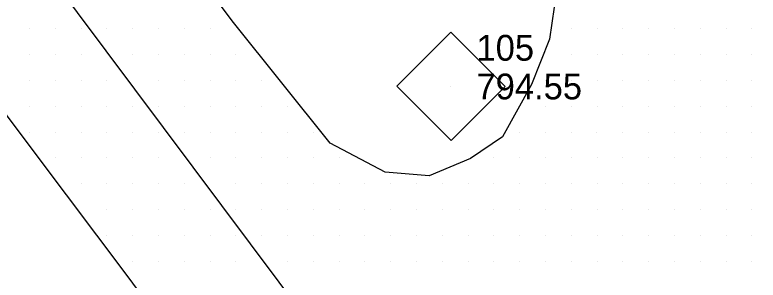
# Model space of a CAD drawing. Extents: x 1762120 to 1766775, y 709485 to 712965.
# Drawn here: x 1763947.3 to 1764019.4, y 711549.4 to 711575.1 of the extents above; entities that cross this region are included whole.
import ezdxf

# ---------------------------------------------------------------- set-up
doc = ezdxf.new("R2010")
doc.units = 0
for name, color, linetype in [('CTL Secondary Horizontal and Vertical CELL', 7, 'Continuous'), ('CTL Secondary Horizontal and Vertical Cogo Elevation', 7, 'Continuous'), ('CTL Secondary Horizontal and Vertical Cogo Number', 7, 'Continuous'), ('Exist DTM Scan Elevation Point', 7, 'Continuous'), ('Exist Roads EOP', 7, 'Continuous'), ('Exist Roads EOT', 7, 'Continuous')]:
    doc.layers.add(name, color=color, linetype=linetype)

msp = doc.modelspace()

# ---------------------------------------------------------------- linework, layer by layer
at = {"layer": 'CTL Secondary Horizontal and Vertical CELL'}
msp.add_line((1763989.569, 711568.173), (1763989.569, 711568.173), dxfattribs=at)
msp.add_lwpolyline([(1763984.354, 711568.191), (1763989.596, 711573.432), (1763994.846, 711568.182), (1763989.604, 711562.94)], close=True, dxfattribs=at)
at = {"layer": 'Exist DTM Scan Elevation Point'}
for p, q in [((1763948.75, 711573.75), (1763948.75, 711573.75)), ((1763951.25, 711573.75), (1763951.25, 711573.75)), ((1763953.75, 711573.75), (1763953.75, 711573.75)), ((1763956.25, 711573.75), (1763956.25, 711573.75)), ((1763958.75, 711573.75), (1763958.75, 711573.75)), ((1763961.25, 711573.75), (1763961.25, 711573.75)), ((1763963.75, 711573.75), (1763963.75, 711573.75)), ((1763966.25, 711573.75), (1763966.25, 711573.75)), ((1764001.25, 711573.75), (1764001.25, 711573.75)), ((1764003.75, 711573.75), (1764003.75, 711573.75)), ((1764006.25, 711573.75), (1764006.25, 711573.75)), ((1764008.75, 711573.75), (1764008.75, 711573.75)), ((1764011.25, 711573.75), (1764011.25, 711573.75)), ((1764013.75, 711573.75), (1764013.75, 711573.75)), ((1764016.25, 711573.75), (1764016.25, 711573.75)), ((1764018.75, 711573.75), (1764018.75, 711573.75)), ((1763948.75, 711571.25), (1763948.75, 711571.25)), ((1763951.25, 711571.25), (1763951.25, 711571.25)), ((1763953.75, 711571.25), (1763953.75, 711571.25)), ((1763958.75, 711571.25), (1763958.75, 711571.25)), ((1763961.25, 711571.25), (1763961.25, 711571.25)), ((1763963.75, 711571.25), (1763963.75, 711571.25)), ((1763966.25, 711571.25), (1763966.25, 711571.25)), ((1763968.75, 711571.25), (1763968.75, 711571.25)), ((1764001.25, 711571.25), (1764001.25, 711571.25)), ((1764003.75, 711571.25), (1764003.75, 711571.25)), ((1764006.25, 711571.25), (1764006.25, 711571.25)), ((1764008.75, 711571.25), (1764008.75, 711571.25)), ((1764011.25, 711571.25), (1764011.25, 711571.25)), ((1764013.75, 711571.25), (1764013.75, 711571.25)), ((1764016.25, 711571.25), (1764016.25, 711571.25)), ((1764018.75, 711571.25), (1764018.75, 711571.25)), ((1763948.75, 711568.75), (1763948.75, 711568.75)), ((1763951.25, 711568.75), (1763951.25, 711568.75)), ((1763953.75, 711568.75), (1763953.75, 711568.75)), ((1763956.25, 711568.75), (1763956.25, 711568.75)), ((1763961.25, 711568.75), (1763961.25, 711568.75)), ((1763963.75, 711568.75), (1763963.75, 711568.75)), ((1763966.25, 711568.75), (1763966.25, 711568.75)), ((1763968.75, 711568.75), (1763968.75, 711568.75)), ((1763971.25, 711568.75), (1763971.25, 711568.75)), ((1763998.75, 711568.75), (1763998.75, 711568.75)), ((1764001.25, 711568.75), (1764001.25, 711568.75)), ((1764003.75, 711568.75), (1764003.75, 711568.75)), ((1764006.25, 711568.75), (1764006.25, 711568.75)), ((1764008.75, 711568.75), (1764008.75, 711568.75)), ((1764011.25, 711568.75), (1764011.25, 711568.75)), ((1764013.75, 711568.75), (1764013.75, 711568.75)), ((1764016.25, 711568.75), (1764016.25, 711568.75)), ((1764018.75, 711568.75), (1764018.75, 711568.75)), ((1763948.75, 711566.25), (1763948.75, 711566.25)), ((1763951.25, 711566.25), (1763951.25, 711566.25)), ((1763953.75, 711566.25), (1763953.75, 711566.25)), ((1763956.25, 711566.25), (1763956.25, 711566.25)), ((1763958.75, 711566.25), (1763958.75, 711566.25)), ((1763961.25, 711566.25), (1763961.25, 711566.25)), ((1763963.75, 711566.25), (1763963.75, 711566.25)), ((1763966.25, 711566.25), (1763966.25, 711566.25)), ((1763968.75, 711566.25), (1763968.75, 711566.25)), ((1763971.25, 711566.25), (1763971.25, 711566.25)), ((1763973.75, 711566.25), (1763973.75, 711566.25)), ((1763998.75, 711566.25), (1763998.75, 711566.25)), ((1764001.25, 711566.25), (1764001.25, 711566.25)), ((1764003.75, 711566.25), (1764003.75, 711566.25)), ((1764006.25, 711566.25), (1764006.25, 711566.25)), ((1764008.75, 711566.25), (1764008.75, 711566.25)), ((1764011.25, 711566.25), (1764011.25, 711566.25)), ((1764013.75, 711566.25), (1764013.75, 711566.25)), ((1764016.25, 711566.25), (1764016.25, 711566.25)), ((1764018.75, 711566.25), (1764018.75, 711566.25)), ((1763948.75, 711563.75), (1763948.75, 711563.75)), ((1763951.25, 711563.75), (1763951.25, 711563.75)), ((1763953.75, 711563.75), (1763953.75, 711563.75)), ((1763956.25, 711563.75), (1763956.25, 711563.75)), ((1763958.75, 711563.75), (1763958.75, 711563.75)), ((1763961.25, 711563.75), (1763961.25, 711563.75)), ((1763963.75, 711563.75), (1763963.75, 711563.75)), ((1763966.25, 711563.75), (1763966.25, 711563.75)), ((1763968.75, 711563.75), (1763968.75, 711563.75)), ((1763971.25, 711563.75), (1763971.25, 711563.75)), ((1763973.75, 711563.75), (1763973.75, 711563.75)), ((1763976.25, 711563.75), (1763976.25, 711563.75)), ((1763996.25, 711563.75), (1763996.25, 711563.75)), ((1763998.75, 711563.75), (1763998.75, 711563.75)), ((1764001.25, 711563.75), (1764001.25, 711563.75)), ((1764003.743, 711563.748), (1764003.743, 711563.748)), ((1764006.25, 711563.75), (1764006.25, 711563.75)), ((1764008.75, 711563.75), (1764008.75, 711563.75)), ((1764011.25, 711563.75), (1764011.25, 711563.75)), ((1764013.75, 711563.75), (1764013.75, 711563.75)), ((1764016.25, 711563.75), (1764016.25, 711563.75)), ((1764018.75, 711563.75), (1764018.75, 711563.75)), ((1763951.25, 711561.25), (1763951.25, 711561.25)), ((1763953.75, 711561.25), (1763953.75, 711561.25)), ((1763956.25, 711561.25), (1763956.25, 711561.25)), ((1763958.75, 711561.25), (1763958.75, 711561.25)), ((1763961.25, 711561.25), (1763961.25, 711561.25)), ((1763966.25, 711561.25), (1763966.25, 711561.25)), ((1763968.75, 711561.25), (1763968.75, 711561.25)), ((1763971.25, 711561.25), (1763971.25, 711561.25)), ((1763973.75, 711561.25), (1763973.75, 711561.25)), ((1763976.25, 711561.25), (1763976.25, 711561.25)), ((1763978.75, 711561.25), (1763978.75, 711561.25)), ((1763993.75, 711561.25), (1763993.75, 711561.25)), ((1763996.25, 711561.25), (1763996.25, 711561.25)), ((1763998.75, 711561.25), (1763998.75, 711561.25)), ((1764001.25, 711561.25), (1764001.25, 711561.25)), ((1764003.75, 711561.25), (1764003.75, 711561.25)), ((1764006.25, 711561.25), (1764006.25, 711561.25)), ((1764008.75, 711561.25), (1764008.75, 711561.25)), ((1764011.25, 711561.25), (1764011.25, 711561.25)), ((1764013.75, 711561.25), (1764013.75, 711561.25)), ((1764016.25, 711561.25), (1764016.25, 711561.25)), ((1764018.75, 711561.25), (1764018.75, 711561.25)), ((1763953.75, 711558.75), (1763953.75, 711558.75)), ((1763956.25, 711558.75), (1763956.25, 711558.75)), ((1763958.75, 711558.75), (1763958.75, 711558.75)), ((1763961.25, 711558.75), (1763961.25, 711558.75)), ((1763963.75, 711558.75), (1763963.75, 711558.75)), ((1763968.75, 711558.75), (1763968.75, 711558.75)), ((1763971.25, 711558.75), (1763971.25, 711558.75)), ((1763973.75, 711558.75), (1763973.75, 711558.75)), ((1763976.25, 711558.75), (1763976.25, 711558.75)), ((1763978.75, 711558.75), (1763978.75, 711558.75)), ((1763981.25, 711558.75), (1763981.25, 711558.75)), ((1763983.75, 711558.75), (1763983.75, 711558.75)), ((1763986.25, 711558.75), (1763986.25, 711558.75)), ((1763988.75, 711558.75), (1763988.75, 711558.75)), ((1763991.25, 711558.75), (1763991.25, 711558.75)), ((1763993.75, 711558.75), (1763993.75, 711558.75)), ((1763996.25, 711558.75), (1763996.25, 711558.75)), ((1763998.75, 711558.75), (1763998.75, 711558.75)), ((1764001.25, 711558.75), (1764001.25, 711558.75)), ((1764003.75, 711558.75), (1764003.75, 711558.75)), ((1764006.25, 711558.75), (1764006.25, 711558.75)), ((1764008.75, 711558.75), (1764008.75, 711558.75)), ((1764011.25, 711558.75), (1764011.25, 711558.75)), ((1764013.75, 711558.75), (1764013.75, 711558.75)), ((1764016.25, 711558.75), (1764016.25, 711558.75)), ((1764018.75, 711558.75), (1764018.75, 711558.75)), ((1763956.25, 711556.25), (1763956.25, 711556.25)), ((1763958.75, 711556.25), (1763958.75, 711556.25)), ((1763961.25, 711556.25), (1763961.25, 711556.25)), ((1763963.75, 711556.25), (1763963.75, 711556.25)), ((1763966.25, 711556.25), (1763966.25, 711556.25)), ((1763968.75, 711556.25), (1763968.75, 711556.25)), ((1763971.25, 711556.25), (1763971.25, 711556.25)), ((1763973.75, 711556.25), (1763973.75, 711556.25)), ((1763976.25, 711556.25), (1763976.25, 711556.25)), ((1763978.75, 711556.25), (1763978.75, 711556.25)), ((1763981.25, 711556.25), (1763981.25, 711556.25)), ((1763983.75, 711556.25), (1763983.75, 711556.25)), ((1763986.25, 711556.25), (1763986.25, 711556.25)), ((1763988.75, 711556.25), (1763988.75, 711556.25)), ((1763991.25, 711556.25), (1763991.25, 711556.25)), ((1763993.75, 711556.25), (1763993.75, 711556.25)), ((1763996.25, 711556.25), (1763996.25, 711556.25)), ((1763998.75, 711556.25), (1763998.75, 711556.25)), ((1764001.25, 711556.25), (1764001.25, 711556.25)), ((1764003.75, 711556.25), (1764003.75, 711556.25)), ((1764006.25, 711556.25), (1764006.25, 711556.25)), ((1764008.75, 711556.25), (1764008.75, 711556.25)), ((1764011.25, 711556.25), (1764011.25, 711556.25)), ((1764013.75, 711556.25), (1764013.75, 711556.25)), ((1764016.25, 711556.25), (1764016.25, 711556.25)), ((1764018.75, 711556.25), (1764018.75, 711556.25)), ((1763956.25, 711553.75), (1763956.25, 711553.75)), ((1763958.75, 711553.75), (1763958.75, 711553.75)), ((1763961.25, 711553.75), (1763961.25, 711553.75)), ((1763963.75, 711553.75), (1763963.75, 711553.75)), ((1763966.25, 711553.75), (1763966.25, 711553.75)), ((1763968.75, 711553.75), (1763968.75, 711553.75)), ((1763971.25, 711553.75), (1763971.25, 711553.75)), ((1763973.75, 711553.75), (1763973.75, 711553.75)), ((1763976.25, 711553.75), (1763976.25, 711553.75)), ((1763978.75, 711553.75), (1763978.75, 711553.75)), ((1763981.25, 711553.75), (1763981.25, 711553.75)), ((1763983.75, 711553.75), (1763983.75, 711553.75)), ((1763986.25, 711553.75), (1763986.25, 711553.75)), ((1763988.747, 711553.749), (1763988.747, 711553.749)), ((1763991.25, 711553.75), (1763991.25, 711553.75)), ((1763993.75, 711553.75), (1763993.75, 711553.75)), ((1763996.25, 711553.75), (1763996.25, 711553.75)), ((1763998.75, 711553.75), (1763998.75, 711553.75)), ((1764001.25, 711553.75), (1764001.25, 711553.75)), ((1764003.75, 711553.75), (1764003.75, 711553.75)), ((1764006.25, 711553.75), (1764006.25, 711553.75)), ((1764008.75, 711553.75), (1764008.75, 711553.75)), ((1764011.25, 711553.75), (1764011.25, 711553.75)), ((1764013.75, 711553.75), (1764013.75, 711553.75)), ((1764016.25, 711553.75), (1764016.25, 711553.75)), ((1764018.75, 711553.75), (1764018.75, 711553.75)), ((1763958.75, 711551.25), (1763958.75, 711551.25)), ((1763961.25, 711551.25), (1763961.25, 711551.25)), ((1763963.75, 711551.25), (1763963.75, 711551.25)), ((1763966.25, 711551.25), (1763966.25, 711551.25)), ((1763968.75, 711551.25), (1763968.75, 711551.25)), ((1763973.75, 711551.25), (1763973.75, 711551.25)), ((1763976.25, 711551.25), (1763976.25, 711551.25)), ((1763978.75, 711551.25), (1763978.75, 711551.25)), ((1763981.25, 711551.25), (1763981.25, 711551.25)), ((1763983.75, 711551.25), (1763983.75, 711551.25)), ((1763986.25, 711551.25), (1763986.25, 711551.25)), ((1763988.75, 711551.25), (1763988.75, 711551.25)), ((1763991.25, 711551.25), (1763991.25, 711551.25)), ((1763993.75, 711551.25), (1763993.75, 711551.25)), ((1763996.25, 711551.25), (1763996.25, 711551.25)), ((1763998.75, 711551.25), (1763998.75, 711551.25)), ((1764001.25, 711551.25), (1764001.25, 711551.25)), ((1764003.75, 711551.25), (1764003.75, 711551.25)), ((1764006.25, 711551.25), (1764006.25, 711551.25)), ((1764008.75, 711551.25), (1764008.75, 711551.25)), ((1764011.25, 711551.25), (1764011.25, 711551.25)), ((1764013.75, 711551.25), (1764013.75, 711551.25)), ((1764016.25, 711551.25), (1764016.25, 711551.25)), ((1764018.75, 711551.25), (1764018.75, 711551.25))]:
    msp.add_line(p, q, dxfattribs=at)
at = {"layer": 'Exist Roads EOP'}
for points in [[(1763990.309, 711636.252), (1763992.745, 711621.666), (1763995.116, 711606.853), (1763997.467, 711592.038), (1763999.037, 711582.597), (1763999.594, 711575.867), (1763999.138, 711572.748), (1763997.406, 711568.373), (1763994.585, 711563.277), (1763991.474, 711561.181), (1763987.464, 711559.513), (1763983.226, 711559.859), (1763977.888, 711562.667), (1763968.516, 711574.388), (1763959.512, 711586.395), (1763950.511, 711598.388), (1763941.411, 711610.306), (1763932.558, 711622.393), (1763928.211, 711628.591)], [(1763902.512, 711623.956), (1763913.274, 711609.7), (1763922.393, 711597.8), (1763931.226, 711585.682), (1763940.241, 711573.699), (1763949.269, 711561.705), (1763958.29, 711549.726), (1763967.178, 711537.645), (1763976.232, 711525.691), (1763985.239, 711513.698), (1763994.091, 711501.562), (1764001.777, 711490.536), (1764004.266, 711485.019), (1764013.177, 711472.947), (1764022.218, 711460.918), (1764026.225, 711454.389), (1764024.836, 711445.749), (1764023.662, 711438.708), (1764016.949, 711432.106)]]:
    msp.add_lwpolyline(points, dxfattribs=at)
at = {"layer": 'Exist Roads EOT'}
msp.add_lwpolyline([(1763916.542, 711624.513), (1763931.478, 711604.596), (1763950.595, 711579.104), (1763975.689, 711545.473)], dxfattribs=at)

# ---------------------------------------------------------------- texts
at = {"layer": 'CTL Secondary Horizontal and Vertical Cogo Elevation'}
msp.add_text('794.55', height=2.5, dxfattribs=at).set_placement((1763992.069, 711566.923))
at = {"layer": 'CTL Secondary Horizontal and Vertical Cogo Number'}
msp.add_text('105', height=2.5, dxfattribs=at).set_placement((1763992.069, 711570.673))

doc.saveas('drawing.dxf')
